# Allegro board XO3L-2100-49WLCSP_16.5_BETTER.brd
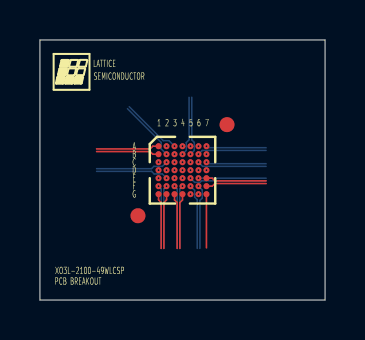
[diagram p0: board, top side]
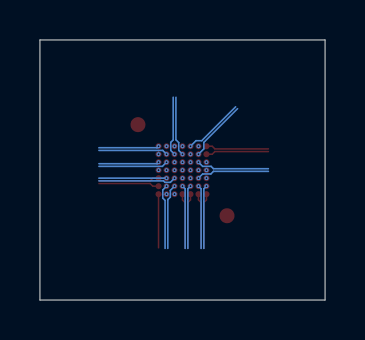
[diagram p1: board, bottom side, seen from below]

Outline 14.28 x 13.02 mm; copper layers: TOP, L2_SIG, L3_PWR_GND, BOTTOM. Coordinates in mm from the lower left corner of the outline.
Outline path: 0,13.02 0,0 14.28,0 14.28,13.02 0,13.02

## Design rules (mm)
net group CDPT20: nets PT20C PT20D
net group CDPT24: nets PT24C PT24D
net group LVDSI_14_PB12: nets LVDSI_14_PB12A LVDSI_14_PB12B
net group LVDSI_23_PB3: nets LVDSI_23_PB3A LVDSI_23_PB3B
net group LVDSI_PB11: nets LVDSI_PB11A LVDSI_PB11B
net group LVDSI_PB16: nets LVDSI_PB16A LVDSI_PB16B
net group LVDSI_PB25: nets LVDSI_PB25A LVDSI_PB25B
net group LVDSO_4_PT17: nets LVDSO_4_PT17A LVDSO_4_PT17B
net group PB8: nets PB8A PB8B
net group PL2: nets PL2A PL2B
net group PL3: nets PL3A PL3B
net group PL5: nets PL5A PL5B
net group PT10: nets PT10A PT10B
net group PT12: nets PT12C PT12D
net group PT16: nets PT16C PT16D
net group PT18: nets PT18C PT18D
net group PT20: nets PT20A PT20B
net group PT23: nets PT23A PT23B
net group PT24: nets PT24A PT24B

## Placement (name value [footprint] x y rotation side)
BGA  -  [BGA49N40P7X7_317X310X60B26N]  7.14 6.5 270 top
NOREF  -  []  0.41 10.21 0 top

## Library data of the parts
BGA = BGA49N40P7X7_317X310X60B26N

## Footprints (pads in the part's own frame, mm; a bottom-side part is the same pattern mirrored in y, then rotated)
BGA49N40P7X7_317X310X60B26N
  round 0.75 smd: (-2.28,2.23) (2.28,-2.23)
  round 0.305 smd: A1(-1.2,-1.2) A2(-1.2,-0.8) A3(-1.2,-0.4) A4(-1.2,0) A5(-1.2,0.4) A6(-1.2,0.8) A7(-1.2,1.2) B1(-0.8,-1.2) B2(-0.8,-0.8) B3(-0.8,-0.4) B4(-0.8,0) B5(-0.8,0.4) B6(-0.8,0.8) B7(-0.8,1.2) C1(-0.4,-1.2) C2(-0.4,-0.8) C3(-0.4,-0.4) C4(-0.4,0) C5(-0.4,0.4) C6(-0.4,0.8) C7(-0.4,1.2) D1(0,-1.2) D2(0,-0.8) D3(0,-0.4) D4(0,0) D5(0,0.4) D6(0,0.8) D7(0,1.2) E1(0.4,-1.2) E2(0.4,-0.8) E3(0.4,-0.4) E4(0.4,0) E5(0.4,0.4) E6(0.4,0.8) E7(0.4,1.2) F1(0.8,-1.2) F2(0.8,-0.8) F3(0.8,-0.4) F4(0.8,0) F5(0.8,0.4) F6(0.8,0.8) F7(0.8,1.2) G1(1.2,-1.2) G2(1.2,-0.8) G3(1.2,-0.4) G4(1.2,0) G5(1.2,0.4) G6(1.2,0.8) G7(1.2,1.2)

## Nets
GND: BGA.A4 BGA.D6 BGA.E1 BGA.G5
VCC: BGA.D1 BGA.D7
VCCIO0: BGA.A2 BGA.A5
VCCIO2: BGA.G6
VCCIO5: BGA.B7
LVDSI_14_PB12A: BGA.F4
LVDSI_14_PB12B: BGA.F3
LVDSI_23_PB3A: BGA.E7
LVDSI_23_PB3B: BGA.F7
LVDSI_PB11A: BGA.E4
LVDSI_PB11B: BGA.E3
LVDSI_PB16A: BGA.G4
LVDSI_PB16B: BGA.G3
LVDSI_PB25A: BGA.G2
LVDSI_PB25B: BGA.G1
LVDSO_4_PT17A: BGA.C4
LVDSO_4_PT17B: BGA.D3
PB5A: BGA.G7
PB8A: BGA.F6
PB8B: BGA.F5
PL2A: BGA.A7
PL2B: BGA.B6
PL3A: BGA.C7
PL3B: BGA.C6
PL5A: BGA.E6
PL5B: BGA.E5
PT10A: BGA.D5
PT10B: BGA.D4
PT12C: BGA.A6
PT12D: BGA.C5
PT16C: BGA.B4
PT16D: BGA.B5
PT18C: BGA.B3
PT18D: BGA.C3
PT20A: BGA.A3
PT20B: BGA.B2
PT20C: BGA.F2
PT20D: BGA.F1
PT23A: BGA.E2
PT23B: BGA.C2
PT24A: BGA.C1
PT24B: BGA.D2
PT24C: BGA.B1
PT24D: BGA.A1

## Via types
v1: diameter 0.203, hole 0.102, TOP to BOTTOM, 40 vias

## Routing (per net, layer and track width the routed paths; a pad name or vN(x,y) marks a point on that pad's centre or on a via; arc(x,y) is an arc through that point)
GND:
  vias: v1(5.94,6.1) v1(7.14,7.7) v1(7.54,5.3) v1(7.94,6.5)
VCC:
  vias: v1(5.94,6.5) v1(8.34,6.5)
VCCIO0:
  vias: v1(6.34,7.7) v1(7.54,7.7)
VCCIO2:
  vias: v1(7.94,5.3)
VCCIO5:
  vias: v1(8.34,7.3)
LVDSI_14_PB12A: length 3.2
  BOTTOM w0.076: 7.01,2.59 7.01,5.57 v1(7.14,5.7)
LVDSI_14_PB12B: length 3.2
  BOTTOM w0.076: 6.87,2.59 6.87,5.57 v1(6.74,5.7)
LVDSI_23_PB3A: length 3
  TOP w0.076: 11.33,5.97 8.76,5.97 8.63,6.1 BGA.E7
LVDSI_23_PB3B: length 3
  TOP w0.076: BGA.F7 8.63,5.7 8.76,5.83 11.33,5.83
LVDSI_PB11A: length 3.7
  L2_SIG w0.076: v1(7.14,6.1) 6.95,5.91 6.95,5.5 6.81,5.36 6.81,2.59
LVDSI_PB11B: length 3.6
  L2_SIG w0.076: v1(6.74,6.1) 6.55,5.91 6.55,5.44 6.68,5.31 6.68,2.59
LVDSI_PB16A: length 2.8
  TOP w0.076: 7.01,2.59 7.01,4.88 7.14,5.01 BGA.G4
LVDSI_PB16B: length 2.8
  TOP w0.076: BGA.G3 6.74,5.01 6.87,4.88 6.87,2.59
LVDSI_PB25A: length 2.8
  TOP w0.076: BGA.G2 6.34,5.01 6.21,4.88 6.21,2.59
LVDSI_PB25B: length 2.8
  TOP w0.076: BGA.G1 5.94,5.01 6.07,4.88 6.07,2.59
LVDSO_4_PT17A: length 3.4
  L2_SIG w0.076: 7.06,10.15 7.06,8.04 7.33,7.78 7.33,7.09 v1(7.14,6.9)
LVDSO_4_PT17B: length 3.7
  L2_SIG w0.076: v1(6.74,6.5) 6.93,6.69 6.93,10.15
PB5A: length 2.7
  TOP w0.076: BGA.G7 8.34,2.62
PB8A: length 3.2
  BOTTOM w0.076: 8.01,2.59 8.01,4.99 8.13,5.1 8.13,5.51 v1(7.94,5.7)
PB8B: length 3.3
  BOTTOM w0.076: 7.88,2.59 7.88,5.03 7.75,5.15 7.75,5.49 v1(7.54,5.7)
PL2A: length 3
  BOTTOM w0.076: 11.33,7.63 8.41,7.63 v1(8.34,7.7)
PL2B: length 3.5
  BOTTOM w0.076: 11.33,7.49 8.13,7.49 v1(7.94,7.3)
PL3A: length 3
  BOTTOM w0.076: v1(8.34,6.9) 8.41,6.83 11.33,6.83
PL3B: length 3.5
  BOTTOM w0.076: v1(7.94,6.9) 8.15,6.69 11.33,6.69
PL5A: length 3.4
  BOTTOM w0.076: v1(7.94,6.1) 11.33,6.1
PL5B: length 3.9
  BOTTOM w0.076: v1(7.54,6.1) 7.75,5.89 8.02,5.89 8.09,5.97 11.33,5.97
PT10A: length 3.9
  L2_SIG w0.076: 11.33,6.17 8.31,6.17 8.19,6.29 7.75,6.29 v1(7.54,6.5)
PT10B: length 4.6
  L2_SIG w0.076: v1(7.14,6.5) 7.35,6.29 7.35,6.02 7.46,5.91 8.2,5.91 8.33,6.04 11.33,6.04
PT12C: length 2.5
  L2_SIG w0.076: 7.86,10.15 7.86,7.98 7.94,7.91 v1(7.94,7.7)
PT12D: length 3.3
  L2_SIG w0.076: v1(7.54,6.9) 7.73,7.09 7.73,10.15
PT16C: length 3
  BOTTOM w0.076: v1(7.14,7.3) 7.33,7.49 7.33,7.88 7.47,8.02 7.47,10.15
PT16D: length 3
  BOTTOM w0.076: 7.6,10.15 7.6,8.02 7.73,7.89 7.73,7.49 v1(7.54,7.3)
PT18C: length 3.4
  L2_SIG w0.076: v1(6.74,7.3) 6.55,7.49 6.2,7.49 4.22,9.47
PT18D: length 3.7
  L2_SIG w0.076: v1(6.74,6.9) 6.53,7.11 6.26,7.11 6.15,7.22 6.15,7.35 6.09,7.41 4.12,9.38
PT20A: length 3.1
  BOTTOM w0.076: 4.48,9.67 6.17,7.98 6.46,7.98 v1(6.74,7.7)
PT20B: length 3.1
  BOTTOM w0.076: v1(6.34,7.3) 6.07,7.57 6.07,7.89 4.38,9.58
PT20C: length 3.2
  BOTTOM w0.076: v1(6.34,5.7) 6.21,5.57 6.21,2.59
PT20D: length 3.2
  BOTTOM w0.076: 6.07,2.59 6.07,5.57 v1(5.94,5.7)
PT23A: length 3.6
  BOTTOM w0.076: v1(6.34,6.1) 6.13,6.31 5.72,6.31 5.59,6.44 2.84,6.44
PT23B: length 3.6
  BOTTOM w0.076: v1(6.34,6.9) 6.13,6.69 5.71,6.69 5.59,6.58 2.84,6.58
PT24A: length 3.3
  L2_SIG w0.076: v1(5.94,6.9) 5.57,6.53 2.84,6.53
PT24B: length 3.6
  L2_SIG w0.076: v1(6.34,6.5) 6.15,6.31 5.65,6.31 5.57,6.4 2.84,6.4
PT24C: length 3.2
  TOP w0.076: 2.84,7.43 5.52,7.43 5.65,7.3 BGA.B1
PT24D: length 3.2
  TOP w0.076: BGA.A1 5.65,7.7 5.52,7.57 2.84,7.57

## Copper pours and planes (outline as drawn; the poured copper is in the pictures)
GND on L3_PWR_GND: 7.22,7.82 7.57,7.47 8.05,7.47 8.05,6.35 7.75,6.35 7.27,6.83 5.67,6.83 5.67,6.27 6,6.27 6.1,6.17 6.1,5.74 7.67,5.74 7.67,4.77 5.46,4.77 5.46,7.39 6.66,7.39 7.09,7.82
VCC on L3_PWR_GND: 5.77,6.73 7.22,6.73 7.65,6.3 8.13,6.3 8.13,6.78 8.87,6.78 8.87,5.84 6.17,5.84 6.17,6.22 6.05,6.35 5.77,6.35
VCCIO0 on L3_PWR_GND: 5.46,7.44 6.58,7.44 7.01,7.87 7.27,7.87 7.57,7.57 8.87,7.57 8.87,8.25 5.46,8.25
VCCIO2 on L3_PWR_GND: 7.77,5.71 7.77,4.77 8.89,4.77 8.89,5.71

Small or netless copper shapes (teardrops, artwork), in the pictures only: 1 on L3_PWR_GND

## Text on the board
User.Comments: ASP | 06/30/14. | DWG NO: | XO3L-2100-49WLCSP | REVISION | 2.0 | SHEET | 1 | OF | XO3L-2100-49WLCSP PCB BREAKOUT | LATTICE SEMICONDUCTOR CORPORATION
Ref Des/Silkscreen Top: PCB BREAKOUT | XO3L-2100-49WLCSP | LATTICE | SEMICONDUCTOR | A | B | C | D | E | F | G | 1 | 2 | 3 | 4 | 5 | 6 | 7
PAGE_OUTLINE: SPECIAL INSTRUCTIONS: | USE 1/2 OUNCE COPPER FOR BOTH INTERNAL AND EXTERNAL LAYERS | VIAS ARE TO BE NON-CONDUCTIVE EPOXY FILLED | PLANARIZE AT TOP AND BOTTOM | BOARD THICKNESS IS 62MILS | SIGNAL         (L2) | POWER/GND PLANE (L3) | PRIMARY SIDE   (L1) | SECONDARY SIDE (L4) | SECONDARY SILKSCREEN | SECONDARY SOLDERMASK | PRIMARY SOLDERMASK | PRIMARY SILKSCREEN | DESIGNED BY: | APPROVED BY: | SIGNATURES         DATE | REV | 1 | INITIAL RELEASE | ESCAPE VIA DRILL | TRACE WIDTH/SPACE | ARRAY SIZE | ESCAPE VIA PAD | BGA LAND OPENING | PACKAGE SIZE | BGA LAND PAD | PITCH | DESCRIPTION | 3.185x3.106 | 0.0762 | 0.0584 | 0.1016 | 0.2032 | 0.3048 | 7 X 7 | 0.40 | MM | MM/DD/YYYY | DATE | 12.00 | 3/2.3 | 15.748 | MILS | 8.00 | 4.00 | APPROVED | XXXXXXXXX | 4 LAYER STACKUP | PCB BREAKOUT DETAILS | REVISION
PLACE_BOUND_TOP: FIGURE | SIZE | 4.0 | ALL UNITS ARE IN MILS | SIZE MM | 0.1016 | PLATED | QTY | 10 | DRILL CHART: TOP to L4_SIG
DISPLAY_TOP: FIGURE | SIZE | 4.0 | ALL UNITS ARE IN MILS | SIZE MM | 0.1016 | PLATED | QTY | 16 | DRILL CHART: TOP to BOTTOM
DEVICE_TYPE_TOP: FIGURE | SIZE | 4.0 | ALL UNITS ARE IN MILS | SIZE MM | 0.1016 | PLATED | QTY | 14 | DRILL CHART: TOP to L3_SIG
